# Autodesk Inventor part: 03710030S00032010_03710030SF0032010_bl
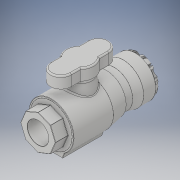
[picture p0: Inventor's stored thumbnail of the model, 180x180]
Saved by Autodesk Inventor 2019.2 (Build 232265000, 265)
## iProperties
Created: 2022-04
Part Number: 03710030S00032010_03710030SF0032010_bl
Material: Generic
Description: PA Ball Valve Series 1 32mm x Female 1''
Document SubType Name: Modeling
Designer: Lenora
Density: 1 g/cm^3
Appearance: Default
Author: Lenora
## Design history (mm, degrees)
derived "0371003.ipt"
feature "Solid1::0371003.ipt" dims "ScaleForDerivedMember" = 10
tag "TaggingFeature1"
body "Solid1"
other parameters: "d0" = 148 [user parameter], "d16" = 88.8 [user parameter], "d19" = 1 [user parameter], "d20" = 37 [user parameter], "d22" = 85 deg [user parameter], "d25" = 1 [user parameter], "d34" = 26.64 [user parameter], "d35" = 14.8 [user parameter], "d37" = 0 [user parameter], "d39" = 360 deg [user parameter], "d43" = 33 [user parameter], "d45" = 70 deg [user parameter], "d46" = 70 deg [user parameter], "d48" = 0 [user parameter], "d57" = 2 [user parameter], "d60" = 25 [user parameter], "d63" = 64 [user parameter], "d71" = 7.4 [user parameter], "d72" = 11.1 [user parameter], "d73" = 26.64 [user parameter], "d76" = 64 [user parameter], "d77" = 19.2 [user parameter], "d78" = 39.96 [user parameter], "d79" = 18.5 [user parameter], "d80" = 100 deg [user parameter], "d81" = 12.58 [user parameter], "d83" = 28.05 [user parameter], "d84" = 11.1 [user parameter], "d85" = 32 [user parameter], "d90" = 0 [user parameter], "d91" = 9.6 [user parameter], "d92" = 45 deg [user parameter], "d93" = 5.12 [user parameter], "d94" = 2.048 [user parameter], "d95" = 2.56 [user parameter], "d96" = 2.56 [user parameter], "d97" = 2.56 [user parameter], "d98" = 2.56 [user parameter], "d111" = 0.5 [user parameter], "d112" = 2 [user parameter], "d114" = 8.96 [user parameter], "d115" = 0 [user parameter], "d117" = 360 deg [user parameter], "d119" = 51.84 [user parameter], "d120" = 58 [user parameter], "d121" = 32 [user parameter], "d122" = 1 [user parameter], "d123" = 89 deg [user parameter], "d124" = 80 deg [user parameter], "d125" = 46 [user parameter], "d127" = 17.6 [user parameter], "d132" = 59.52 [user parameter], "d134" = 0 [user parameter], "d135" = 0.25 [user parameter], "d138" = 30.291 [user parameter], "d139" = 22 [user parameter], "d" = 32 [user parameter], "DN" = 25 [user parameter], "A1" = 33 [user parameter], "A2" = 64 [user parameter], "H_" = 148 [user parameter], "E_" = 64 [user parameter], "E1" = 58 [user parameter], "B" = 46 [user parameter], "l2" = 22 [user parameter], "Rc" = 30.291 [user parameter]
